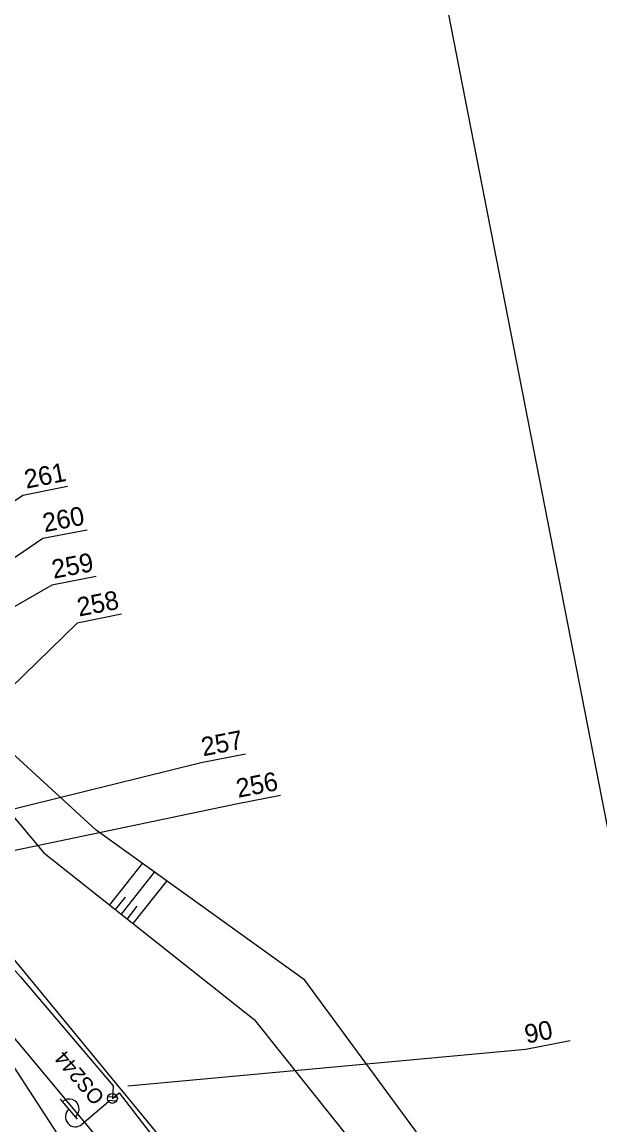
# Model space of a CAD drawing. Extents: x -545846 to -545044, y -1122650 to -1119108.
# Drawn here: x -545544.2 to -545486.4, y -1119489.2 to -1119378.9 of the extents above; entities that cross this region are included whole.
import ezdxf

# ---------------------------------------------------------------- set-up
doc = ezdxf.new("R2010")
doc.units = 0
for name, color, linetype in [('osvětlené plochy-hodnota-obrys', 7, 'Continuous'), ('so180602', 7, 'Continuous'), ('Vrstva 1', 7, 'Continuous'), ('Vrstva 10', 7, 'Continuous'), ('Vrstva 25', 7, 'Continuous'), ('Vrstva 26', 7, 'Continuous'), ('Vrstva 48', 7, 'Continuous'), ('Vrstva 49', 7, 'Continuous'), ('Vrstva 63', 7, 'Continuous')]:
    doc.layers.add(name, color=color, linetype=linetype)

msp = doc.modelspace()

# ---------------------------------------------------------------- linework, layer by layer
at = {"layer": 'osvětlené plochy-hodnota-obrys'}
msp.add_lwpolyline([(-545610.46, -1119381.57), (-545587.49, -1119421.11), (-545524.22, -1119497.93), (-545520.97, -1119506.47)], dxfattribs=at)
at = {"layer": 'Vrstva 1'}
for points in [[(-545591.41, -1119423.7), (-545583.65, -1119433.78), (-545578.82, -1119439.95), (-545578.04, -1119440.89), (-545571.05, -1119449.89), (-545562.9, -1119459.46), (-545560.93, -1119461.76), (-545560.13, -1119462.7), (-545552.78, -1119471.36), (-545544.6, -1119481), (-545536.08, -1119491.22), (-545529.55, -1119500.44), (-545524.24, -1119509.31), (-545520.74, -1119516)], [(-545552.78, -1119471.36), (-545545.93, -1119482.02), (-545538.69, -1119493.23), (-545532.97, -1119502.55), (-545528.01, -1119511.68), (-545525.02, -1119517.83)]]:
    msp.add_lwpolyline(points, dxfattribs=at)
at = {"layer": 'Vrstva 10'}
msp.add_line((-545554.37, -1119108.31), (-545292.19, -1120447.89), dxfattribs=at)
at = {"layer": 'Vrstva 25'}
for p, q in [((-545534.7, -1119486.44), (-545535.65, -1119486.37)), ((-545538.69, -1119488.61), (-545540.37, -1119486.63)), ((-545535.57, -1119486.87), (-545538.23, -1119489.14)), ((-545534.77, -1119486.81), (-545535.64, -1119486.74))]:
    msp.add_line(p, q, dxfattribs=at)
msp.add_circle((-545535.19, -1119486.54), 0.5, dxfattribs=at)
msp.add_circle((-545535.19, -1119486.54), 0.5, dxfattribs=at)
for centre, start, end in [((-545539.52, -1119487.61), 309.7286, 131.1337), ((-545538.88, -1119488.38), 130.4312, 310.4312)]:
    msp.add_arc(centre, 1, start, end, dxfattribs=at)
at = {"layer": 'Vrstva 26'}
msp.add_lwpolyline([(-545613.61, -1119473.78), (-545613.5, -1119472.8), (-545577.43, -1119463.6), (-545557.75, -1119458.58), (-545557.45, -1119459.45), (-545554.38, -1119463.21), (-545544.39, -1119474.38), (-545535.11, -1119485.28), (-545535.19, -1119486.54), (-545534.52, -1119485.98), (-545528.13, -1119494.27)], dxfattribs=at)
at = {"layer": 'Vrstva 48'}
for p, q in [((-545535.45, -1119467.19), (-545532.18, -1119463.06)), ((-545534.28, -1119468.12), (-545530.96, -1119463.93)), ((-545533.1, -1119469.05), (-545529.74, -1119464.81)), ((-545534.86, -1119467.66), (-545533.87, -1119466.41)), ((-545533.69, -1119468.59), (-545532.69, -1119467.32))]:
    msp.add_line(p, q, dxfattribs=at)
at = {"layer": 'Vrstva 49'}
for points in [[(-545619.99, -1119314.3), (-545614.88, -1119338.94), (-545608.59, -1119358.46), (-545591.92, -1119397.51), (-545579.96, -1119416.57), (-545563.33, -1119436.59), (-545542.04, -1119461.97), (-545521.01, -1119478.64), (-545502.28, -1119502.1)], [(-545498.44, -1119498.5), (-545515.94, -1119474.72), (-545536.81, -1119459.72), (-545562.24, -1119436.4), (-545577.43, -1119413.24), (-545589.26, -1119395.3), (-545595.47, -1119360.87)]]:
    msp.add_lwpolyline(points, dxfattribs=at)
at = {"layer": 'Vrstva 63'}
for p, q in [((-545539.69, -1119425.35), (-545544.13, -1119426.22)), ((-545539.69, -1119425.35), (-545544.13, -1119426.22)), ((-545539.69, -1119425.35), (-545544.13, -1119426.22)), ((-545544.13, -1119426.22), (-545595.62, -1119460.4)), ((-545537.71, -1119429.69), (-545542.16, -1119430.55)), ((-545537.71, -1119429.69), (-545542.16, -1119430.55)), ((-545537.71, -1119429.69), (-545542.16, -1119430.55)), ((-545542.16, -1119430.55), (-545581.23, -1119457.16)), ((-545536.8, -1119434.35), (-545541.25, -1119435.21)), ((-545536.8, -1119434.35), (-545541.25, -1119435.21)), ((-545536.8, -1119434.35), (-545541.25, -1119435.21)), ((-545541.25, -1119435.21), (-545572.5, -1119453.23)), ((-545538.71, -1119438.99), (-545558.04, -1119457.8)), ((-545534.26, -1119438.12), (-545538.71, -1119438.99)), ((-545534.26, -1119438.12), (-545538.71, -1119438.99)), ((-545534.26, -1119438.12), (-545538.71, -1119438.99)), ((-545521.86, -1119452.11), (-545526.3, -1119452.97)), ((-545521.86, -1119452.11), (-545526.3, -1119452.97)), ((-545521.86, -1119452.11), (-545526.3, -1119452.97)), ((-545526.3, -1119452.97), (-545566.69, -1119462.96)), ((-545518.35, -1119456.26), (-545522.79, -1119457.12)), ((-545518.35, -1119456.26), (-545522.79, -1119457.12)), ((-545518.35, -1119456.26), (-545522.79, -1119457.12)), ((-545522.79, -1119457.12), (-545594.6, -1119472.11)), ((-545489.37, -1119480.79), (-545493.81, -1119481.66)), ((-545493.81, -1119481.66), (-545533.65, -1119485.32))]:
    msp.add_line(p, q, dxfattribs=at)

# ---------------------------------------------------------------- texts
at = {"layer": 'so180602'}
for s, p in [('261', (-545543.8, -1119425.56)), ('260', (-545541.97, -1119429.92)), ('259', (-545541.06, -1119434.57)), ('258', (-545538.52, -1119438.35)), ('257', (-545526.1, -1119452.33)), ('256', (-545522.6, -1119456.48)), ('90', (-545493.75, -1119481.07))]:
    msp.add_text(s, height=1.875, rotation=10.9955, dxfattribs=at).set_placement(p)
at = {"layer": 'Vrstva 25'}
msp.add_text('OS244', height=1.5, rotation=130.4312, dxfattribs=at).set_placement((-545535.88, -1119486.38))

doc.saveas('drawing.dxf')
